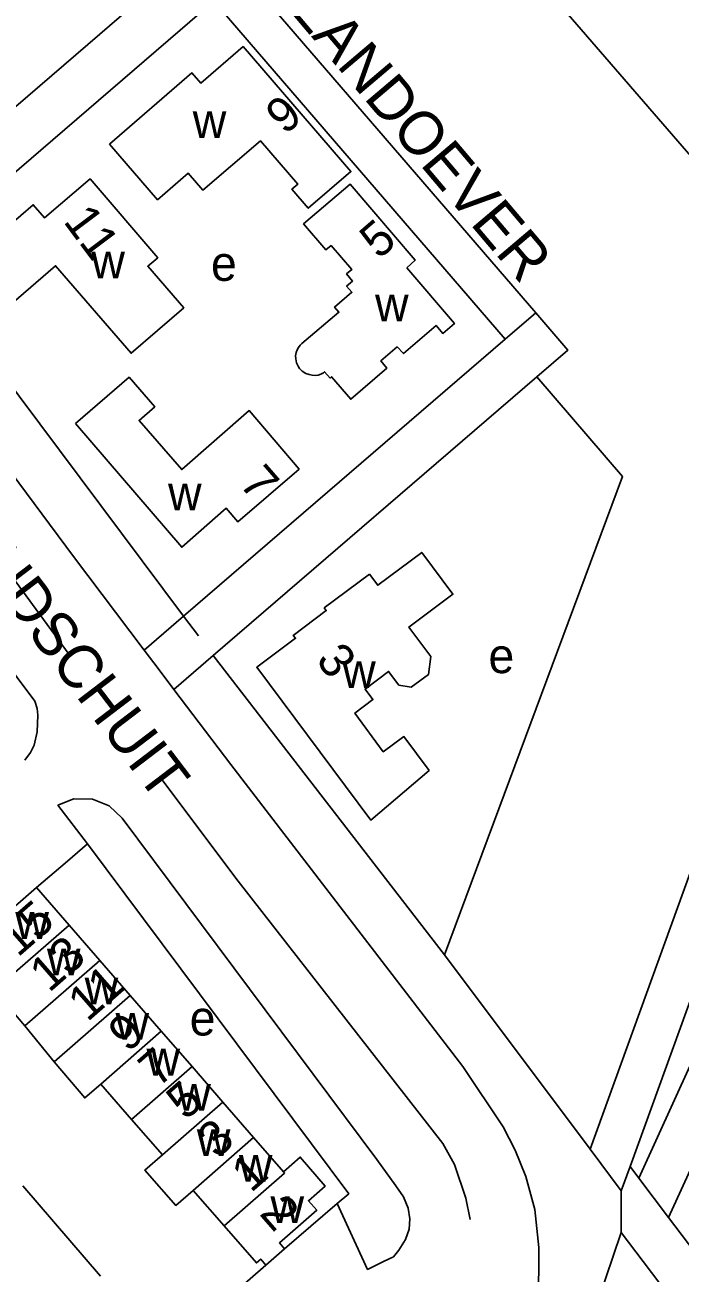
# Model space of a CAD drawing. Extents: x 155854 to 157362, y 383621 to 384685.
# Drawn here: x 156769.5 to 156844.9, y 384304.4 to 384447.9 of the extents above; entities that cross this region are included whole.
import ezdxf

# ---------------------------------------------------------------- set-up
doc = ezdxf.new("R2010")
doc.units = 0
for name, color, linetype in [('BLT_Basislijn', 7, 'Continuous'), ('BLT_Bebouwing', 7, 'Continuous'), ('BLT_Centroide', 7, 'Continuous'), ('BLT_Huisnummer', 7, 'Continuous'), ('BLT_Huisnummer_ tussenligend', 7, 'Continuous'), ('BLT_Onderverdeling_panden', 7, 'Continuous'), ('BLT_Straatnaam', 7, 'Continuous'), ('BLT_Vlakafsluiter', 7, 'Continuous')]:
    doc.layers.add(name, color=color, linetype=linetype)

msp = doc.modelspace()

# ---------------------------------------------------------------- linework, layer by layer
at = {"layer": 'BLT_Basislijn'}
for p, q in [((156824.78, 384411.77), (156828.31, 384414.81)), ((156857.23, 384381.29), (156834.56, 384318.6)), ((156840.16, 384315.3), (156869.72, 384380.17)), ((156783.25, 384376.02), (156787.78, 384379.92)), ((156787.78, 384379.92), (156789.48, 384377.65)), ((156860.98, 384376.94), (156839.16, 384316.62)), ((156791.19, 384375.38), (156786.67, 384371.5)), ((156786.67, 384371.5), (156784.96, 384373.76)), ((156776.72, 384353.73), (156773.32, 384358.18)), ((156776.72, 384353.73), (156774.4, 384351.73)), ((156774.4, 384351.73), (156770.85, 384348.72)), ((156860.3, 384347.45), (156843.58, 384310.76)), ((156834.56, 384318.6), (156838.15, 384313.82)), ((156839.16, 384316.62), (156838.15, 384313.82)), ((156840.16, 384315.3), (156839.16, 384316.62)), ((156769.28, 384314.39), (156778.23, 384304.02)), ((156843.58, 384310.76), (156840.16, 384315.3)), ((156838.15, 384313.82), (156838.15, 384309.04)), ((156805.47, 384312.36), (156799.4, 384307.16)), ((156852.75, 384298.63), (156843.58, 384310.76)), ((156838.15, 384309.04), (156834.9, 384299.45)), ((156850.15, 384293.23), (156838.15, 384309.04)), ((156797.26, 384305.29), (156785.78, 384295.31))]:
    msp.add_line(p, q, dxfattribs=at)
for points in [[(156828.31, 384414.81), (156754.83, 384499.98)], [(156753.52, 384425.7), (156787.55, 384455)], [(156791.25, 384450.67), (156756.91, 384421.13)], [(156824.78, 384411.77), (156791.25, 384450.67)], [(156830.82, 384450.53), (156854.55, 384423.14), (156867.14, 384408.69)], [(156756.91, 384421.13), (156787.78, 384379.92)], [(156783.25, 384376.02), (156775.11, 384386.78), (156752.44, 384417.28)], [(156828.42, 384407.44), (156832.01, 384410.52), (156828.31, 384414.81)], [(156787.78, 384379.92), (156824.78, 384411.77)], [(156748.79, 384410.18), (156765.84, 384387.43), (156774.6, 384375.51)], [(156828.42, 384407.44), (156791.19, 384375.38)], [(156817.79, 384340.96), (156838.27, 384396), (156828.42, 384407.44)], [(156769.52, 384363.37), (156770.14, 384364.24), (156770.6, 384365.09), (156770.91, 384366.62), (156771.02, 384368.53), (156770.93, 384369.3), (156770.65, 384370.13), (156745.65, 384403.58), (156745, 384404.11), (156744.24, 384404.39), (156743.4, 384404.47), (156742.3, 384404.45), (156741.1, 384404.22), (156740.37, 384403.99), (156739.51, 384403.53)], [(156791.19, 384375.38), (156817.79, 384340.96)], [(156824.56, 384321.19), (156819.92, 384328.12), (156793.22, 384362.85), (156786.67, 384371.5)], [(156785.15, 384361.29), (156794.06, 384349.45), (156817.6, 384319.28)], [(156773.32, 384358.18), (156775.16, 384358.9), (156777.31, 384358.88), (156779.21, 384358.1), (156780.7, 384356.67)], [(156780.7, 384356.67), (156795.36, 384337.05), (156810.03, 384317.44)], [(156776.72, 384353.73), (156806.78, 384313.49), (156805.47, 384312.36)], [(156817.79, 384340.96), (156834.56, 384318.6)], [(156827.74, 384296.18), (156828.62, 384300.77), (156828.66, 384307.31), (156828.18, 384311.66), (156827.18, 384315.47), (156825.95, 384318.52), (156824.56, 384321.19)], [(156817.6, 384319.28), (156818.96, 384316.84), (156820.26, 384313), (156820.74, 384310.53)], [(156810.03, 384317.44), (156812.19, 384314.41), (156813.1, 384313.14), (156813.63, 384311.82), (156813.8, 384310.59), (156813.74, 384309.42), (156813.31, 384308.24), (156812.55, 384306.99), (156811.92, 384306.23), (156810.79, 384305.68), (156808.95, 384304.79), (156805.47, 384312.36)]]:
    msp.add_lwpolyline(points, dxfattribs=at)
at = {"layer": 'BLT_Bebouwing'}
for p, q in [((156770.85, 384348.72), (156762.21, 384341.2)), ((156769.52, 384332.81), (156772.89, 384328.68)), ((156799.26, 384316.02), (156795.84, 384319.96))]:
    msp.add_line(p, q, dxfattribs=at)
for points in [[(156779.26, 384434.22), (156788.74, 384442.4), (156789.75, 384441.24), (156794.62, 384445.44), (156807.03, 384431.06), (156802.13, 384426.84), (156800.25, 384429.02), (156800.92, 384429.6), (156796.61, 384434.61), (156790, 384428.91), (156788.31, 384430.86), (156784.78, 384427.82)], [(156775.32, 384402.08), (156781.51, 384407.4), (156784.46, 384404.01), (156782.65, 384402.43), (156787.56, 384396.79), (156795.33, 384403.57), (156801.06, 384396.83), (156794.01, 384390.78), (156792.68, 384392.34), (156787.57, 384387.85)], [(156809.17, 384384.75), (156810.12, 384383.47), (156815.19, 384387.25), (156818.77, 384382.44), (156813.7, 384378.67), (156816.23, 384375.28), (156815.95, 384373.21), (156813.98, 384371.75), (156812.55, 384371.99), (156811.37, 384373.57), (156808.67, 384371.54), (156809.57, 384370.33), (156807.5, 384368.77), (156810.76, 384364.33), (156813.13, 384366.08), (156816.02, 384362.18), (156809.33, 384356.44), (156796.19, 384374.04), (156800.66, 384377.38), (156800.4, 384377.7), (156804.2, 384380.57), (156803.97, 384380.88)]]:
    msp.add_lwpolyline(points, close=True, dxfattribs=at)
for points in [[(156761.92, 384419.87), (156770.48, 384427.24), (156771.78, 384425.72), (156777.01, 384430.22), (156784.81, 384421.15), (156783.66, 384420.16), (156787.79, 384415.39), (156781.74, 384410.16), (156773.05, 384420.23), (156766.46, 384414.57), (156761.91, 384419.87)], [(156813.46, 384420), (156818.95, 384413.58), (156817.61, 384412.45), (156816.84, 384413.36), (156813.09, 384410.12), (156812.37, 384410.89), (156810.47, 384409.28), (156811.18, 384408.46), (156807.01, 384404.87), (156804.81, 384407.46), (156804.64, 384407.31), (156804.01, 384408.04), (156803.86, 384407.9), (156803.57, 384407.75), (156803.26, 384407.66), (156802.91, 384407.61), (156802.57, 384407.63), (156802.21, 384407.7), (156801.83, 384407.83), (156801.43, 384408.09), (156801.13, 384408.41), (156800.99, 384408.61), (156800.77, 384409.06), (156800.68, 384409.52), (156800.67, 384409.85), (156800.73, 384410.23), (156800.85, 384410.56), (156800.99, 384410.84), (156801.19, 384411.09), (156801.39, 384411.3), (156805.66, 384414.88), (156805.16, 384415.47), (156807.14, 384417.17), (156806.54, 384417.87), (156807.23, 384418.46), (156806.53, 384419.28), (156807.12, 384419.78), (156804.75, 384422.54), (156804.16, 384422.04), (156801.59, 384425.03), (156806.93, 384429.62), (156814.44, 384420.87), (156813.46, 384420)], [(156774.6, 384344.4), (156770.85, 384348.72)], [(156778.13, 384340.33), (156774.6, 384344.4)], [(156781.63, 384336.31), (156778.13, 384340.33)], [(156765.97, 384336.89), (156769.52, 384332.81)], [(156785.21, 384332.18), (156781.63, 384336.31)], [(156788.76, 384328.11), (156785.21, 384332.18)], [(156772.89, 384328.68), (156776.4, 384324.51), (156778.25, 384326.1)], [(156792.3, 384324.03), (156788.76, 384328.11)], [(156778.25, 384326.1), (156781.79, 384322.03)], [(156795.84, 384319.96), (156792.3, 384324.03)], [(156781.79, 384322.03), (156785.34, 384317.95)], [(156785.34, 384317.95), (156783.33, 384316.22), (156786.88, 384312.15), (156788.89, 384313.88)], [(156799.4, 384307.16), (156798.81, 384307.84), (156803.11, 384311.59), (156802.15, 384312.69), (156804.08, 384314.37), (156801.2, 384317.7), (156799.26, 384316.02)], [(156788.89, 384313.88), (156792.44, 384309.8)], [(156792.44, 384309.8), (156796.16, 384305.53), (156796.66, 384305.97), (156797.26, 384305.29)], [(156797.26, 384305.29), (156799.4, 384307.16)]]:
    msp.add_lwpolyline(points, dxfattribs=at)
at = {"layer": 'BLT_Onderverdeling_panden'}
for p, q in [((156765.97, 384336.89), (156774.6, 384344.4)), ((156769.52, 384332.81), (156778.13, 384340.33)), ((156772.89, 384328.68), (156781.63, 384336.31)), ((156778.25, 384326.1), (156785.21, 384332.18)), ((156781.79, 384322.03), (156788.76, 384328.11)), ((156785.34, 384317.95), (156792.3, 384324.03)), ((156788.89, 384313.88), (156795.84, 384319.96))]:
    msp.add_line(p, q, dxfattribs=at)
msp.add_lwpolyline([(156792.44, 384309.8), (156799.4, 384315.86), (156799.26, 384316.02)], dxfattribs=at)
at = {"layer": 'BLT_Vlakafsluiter'}
msp.add_line((156784.96, 384373.76), (156783.25, 384376.02), dxfattribs=at)

# ---------------------------------------------------------------- texts
at = {"layer": 'BLT_Centroide'}
for s, p in [('w', (156788.83, 384434.91)), ('w', (156777.16, 384418.76)), ('e', (156790.93, 384418.49)), ('w', (156809.81, 384413.84)), ('w', (156785.99, 384392.1)), ('e', (156822.86, 384373.37)), ('w', (156806.03, 384371.67)), ('w', (156768.41, 384342.81)), ('w', (156772.05, 384338.62)), ('w', (156776.39, 384335.28)), ('w', (156779.94, 384331.22)), ('e', (156788.48, 384331.69)), ('w', (156783.51, 384327.09)), ('w', (156787.05, 384323.03)), ('w', (156789.3, 384317.84)), ('w', (156794.14, 384314.88)), ('w', (156797.78, 384310.11))]:
    msp.add_text(s, height=4, dxfattribs=at).set_placement(p)
at = {"layer": 'BLT_Huisnummer'}
for s, rotation, p in [('9', 40.8266, (156799.44, 384435.19)), ('11', 306.8181, (156773.85, 384425.32)), ('5', 40.7843, (156810.25, 384420.88)), ('7', 311.0112, (156794.06, 384395.09)), ('3', 306.7596, (156802.91, 384374.86)), ('15', 41.144, (156768.7, 384340.61)), ('11', 41.144, (156776.7, 384333.18)), ('7', 41.144, (156784.82, 384325.61)), ('3', 41.144, (156791.63, 384317.45)), ('2', 311.1423, (156796.4, 384311.16))]:
    msp.add_text(s, height=4, rotation=rotation, dxfattribs=at).set_placement(p)
at = {"layer": 'BLT_Huisnummer_ tussenligend'}
for s, p in [('13', (156772.29, 384336.54)), ('9', (156781.34, 384329.65)), ('5', (156788.01, 384321.85)), ('1', (156795.52, 384313.52))]:
    msp.add_text(s, height=4, rotation=41.144, dxfattribs=at).set_placement(p)
at = {"layer": 'BLT_Straatnaam'}
for s, rotation, p in [('ZANDOEVER', 310.2609, (156799.77, 384449.74)), ('ZANDSCHUIT', 307.2809, (156758.65, 384392.66))]:
    msp.add_text(s, height=5, rotation=rotation, dxfattribs=at).set_placement(p)

doc.saveas('drawing.dxf')
